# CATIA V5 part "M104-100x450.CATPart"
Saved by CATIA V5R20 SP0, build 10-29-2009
Part number: M104-100x450
Source: Unknown
Bounding box of the stored display mesh (mm): x -49.986 to 49.986, y -49.986 to 49.986, z 0 to 450
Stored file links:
  C:\Users\Utente\Desktop\IO LAVORO\3D X SITO CF\X SITO\M104\M104-100x450.CATPart
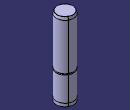
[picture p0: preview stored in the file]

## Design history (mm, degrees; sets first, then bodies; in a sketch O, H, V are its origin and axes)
Body1 (main body)
  Solid1 "PartBody": solid without history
